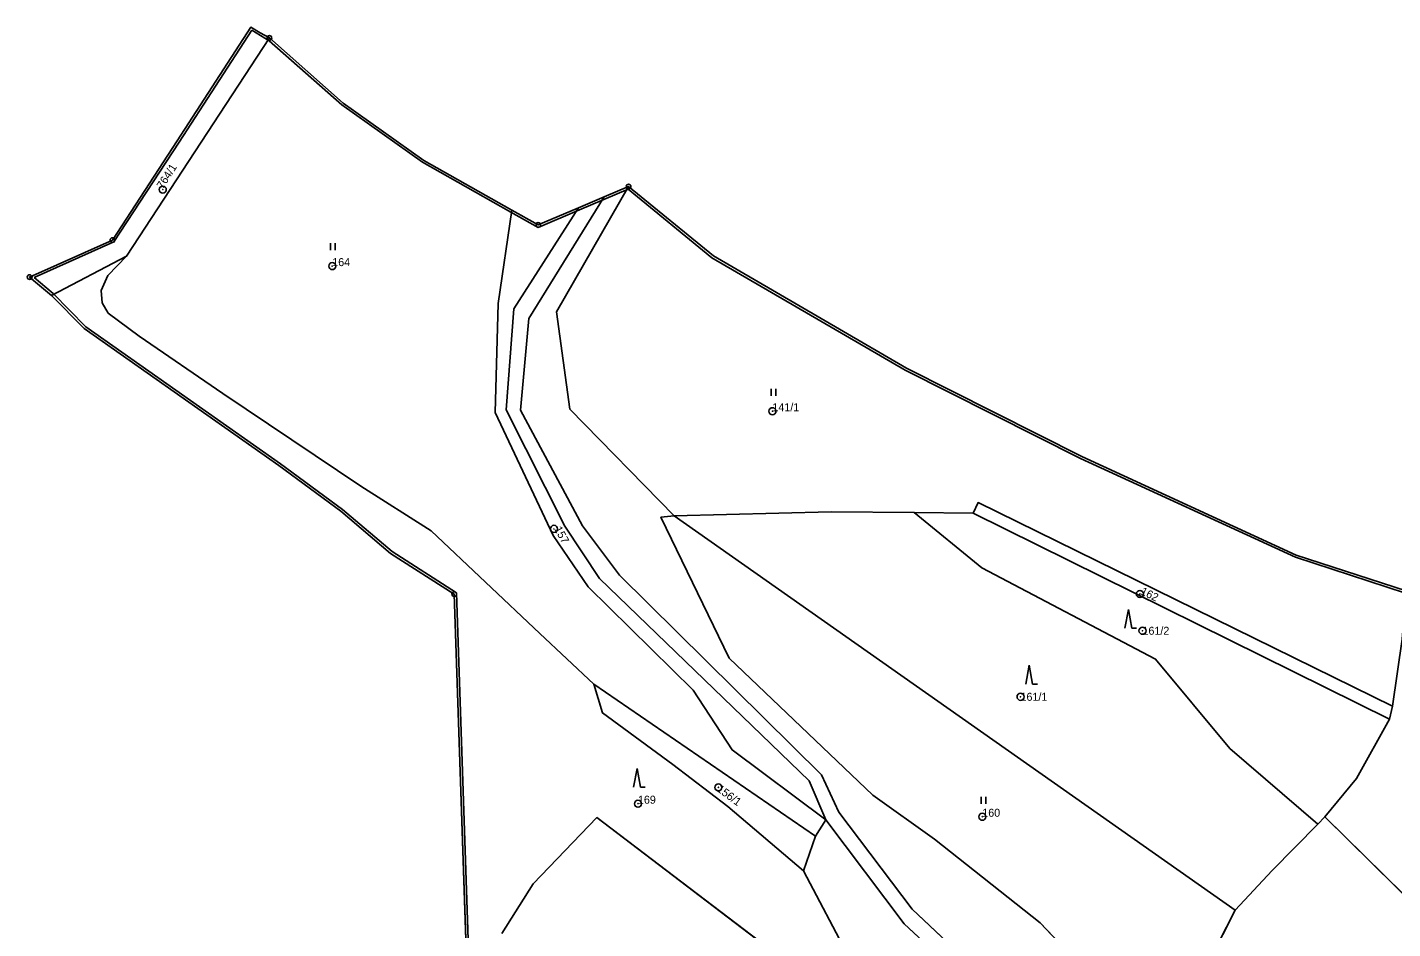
# Model space of a CAD drawing. Extents: x -652854 to -650068, y -1097661 to -1095417.
# Drawn here: x -651109.6 to -650819.6, y -1095608.5 to -1095417 of the extents above; entities that cross this region are included whole.
import ezdxf

# ---------------------------------------------------------------- set-up
doc = ezdxf.new("R2010")
doc.units = 0
for name, color, linetype in [('Definiční body parcel', 7, 'Continuous'), ('Geodetické body', 7, 'Continuous'), ('Hranice obcí', 7, 'Continuous'), ('Hranice parcel', 7, 'Continuous'), ('Obvody jako plochy', 7, 'Continuous'), ('Ostatní hranice', 7, 'Continuous'), ('Parcelní čísla', 7, 'Continuous'), ('Značky kultur', 7, 'Continuous')]:
    doc.layers.add(name, color=color, linetype=linetype)

msp = doc.modelspace()

# ---------------------------------------------------------------- linework, layer by layer
at = {"layer": 'Definiční body parcel'}
for centre, radius in [((-651080.86, -1095451.52), 0.75), ((-651080.86, -1095451.52), 0.0327), ((-651044.86, -1095467.77), 0.75), ((-651044.86, -1095467.77), 0.0327), ((-650951.35, -1095498.59), 0.75), ((-650951.35, -1095498.59), 0.0327), ((-650997.76, -1095523.58), 0.75), ((-650997.76, -1095523.58), 0.0327), ((-650873.29, -1095537.42), 0.75), ((-650873.29, -1095537.42), 0.0327), ((-650872.74, -1095545.23), 0.75), ((-650872.74, -1095545.23), 0.0327), ((-650898.65, -1095559.26), 0.75), ((-650898.65, -1095559.26), 0.0327), ((-650962.83, -1095578.5), 0.75), ((-650962.83, -1095578.5), 0.0327), ((-650979.92, -1095581.97), 0.75), ((-650979.92, -1095581.97), 0.0327), ((-650906.77, -1095584.74), 0.75), ((-650906.77, -1095584.74), 0.0327)]:
    msp.add_circle(centre, radius, dxfattribs=at)
at = {"layer": 'Geodetické body'}
for centre, radius in [((-651058.22, -1095419.3), 0.5), ((-651058.22, -1095419.3), 0.001), ((-650981.9, -1095450.86), 0.5), ((-650981.9, -1095450.86), 0.001), ((-651001.11, -1095459.02), 0.5), ((-651001.11, -1095459.02), 0.001), ((-651091.57, -1095462.24), 0.5), ((-651091.57, -1095462.24), 0.001), ((-651109.14, -1095470.11), 0.5), ((-651109.14, -1095470.11), 0.001), ((-651018.95, -1095537.44), 0.5), ((-651018.95, -1095537.44), 0.001)]:
    msp.add_circle(centre, radius, dxfattribs=at)
at = {"layer": 'Hranice obcí'}
for p, q in [((-651077.8, -1095441.16), (-651062.16, -1095417.04)), ((-651062.16, -1095417.04), (-651060.16, -1095418.18)), ((-651060.16, -1095418.18), (-651058.22, -1095419.3)), ((-651058.22, -1095419.3), (-651042.54, -1095433.15)), ((-651042.54, -1095433.15), (-651025.41, -1095445.31)), ((-651091.57, -1095462.24), (-651077.8, -1095441.16)), ((-651006.69, -1095455.87), (-651025.41, -1095445.31)), ((-650987.13, -1095453.08), (-650981.9, -1095450.86)), ((-650981.9, -1095450.86), (-650963.9, -1095465.61)), ((-650992.58, -1095455.4), (-650987.13, -1095453.08)), ((-651001.11, -1095459.02), (-651006.69, -1095455.87)), ((-651001.11, -1095459.02), (-650992.58, -1095455.4)), ((-651109.14, -1095470.11), (-651091.57, -1095462.24)), ((-650963.9, -1095465.61), (-650922.86, -1095489.44)), ((-651104.47, -1095473.99), (-651109.14, -1095470.11)), ((-651097.54, -1095481.04), (-651104.47, -1095473.99)), ((-651056.2, -1095510.14), (-651097.54, -1095481.04)), ((-650922.86, -1095489.44), (-650885.63, -1095508.23)), ((-651043.02, -1095519.86), (-651056.2, -1095510.14)), ((-650885.63, -1095508.23), (-650840.07, -1095529.15)), ((-651032.46, -1095528.83), (-651043.02, -1095519.86)), ((-651018.95, -1095537.44), (-651032.46, -1095528.83)), ((-650840.07, -1095529.15), (-650816.7, -1095536.76)), ((-651016.16, -1095621.12), (-651018.95, -1095537.44))]:
    msp.add_line(p, q, dxfattribs=at)
at = {"layer": 'Hranice parcel'}
for p, q in [((-651058.22, -1095419.3), (-651088.54, -1095465.64)), ((-650997.25, -1095477.5), (-650981.9, -1095450.86)), ((-651003.09, -1095478.89), (-650987.13, -1095453.08)), ((-651009.63, -1095475.69), (-651006.69, -1095455.87)), ((-651006.31, -1095476.83), (-650992.58, -1095455.4)), ((-651088.54, -1095465.64), (-651104.47, -1095473.99)), ((-651088.54, -1095465.64), (-651092.5, -1095469.77)), ((-651092.5, -1095469.77), (-651093.95, -1095472.98)), ((-651093.95, -1095472.98), (-651093.72, -1095475.56)), ((-651093.72, -1095475.56), (-651092.46, -1095477.73)), ((-651092.46, -1095477.73), (-651085.87, -1095482.66)), ((-651010.22, -1095498.84), (-651009.63, -1095475.69)), ((-651007.89, -1095498.28), (-651006.31, -1095476.83)), ((-650994.36, -1095498.19), (-650997.25, -1095477.5)), ((-651004.85, -1095498.37), (-651003.09, -1095478.89)), ((-651085.87, -1095482.66), (-651068.08, -1095494.82)), ((-651068.08, -1095494.82), (-651038.82, -1095514.5)), ((-650995.44, -1095522.98), (-651007.89, -1095498.28)), ((-650991.71, -1095522.97), (-651004.85, -1095498.37)), ((-650972.25, -1095520.85), (-650994.36, -1095498.19)), ((-650997.94, -1095525.03), (-651010.22, -1095498.84)), ((-651038.82, -1095514.5), (-651023.83, -1095523.99)), ((-650907.68, -1095517.99), (-650908.72, -1095520.28)), ((-650819.64, -1095561.23), (-650907.68, -1095517.99)), ((-650972.25, -1095520.85), (-650975.04, -1095521.11)), ((-650975.04, -1095521.11), (-650960.55, -1095551.05)), ((-650938.89, -1095519.94), (-650972.25, -1095520.85)), ((-650972.25, -1095520.85), (-650853.09, -1095604.56)), ((-650921.24, -1095520.14), (-650938.89, -1095519.94)), ((-650908.72, -1095520.28), (-650921.24, -1095520.14)), ((-650921.24, -1095520.14), (-650906.89, -1095531.86)), ((-650908.72, -1095520.28), (-650820.27, -1095563.98)), ((-651023.83, -1095523.99), (-651000.77, -1095545.83)), ((-650988.07, -1095534.16), (-650995.44, -1095522.98)), ((-650983.87, -1095533.43), (-650991.71, -1095522.97)), ((-650990.49, -1095535.87), (-650997.94, -1095525.03)), ((-650940.93, -1095575.82), (-650983.87, -1095533.43)), ((-650906.89, -1095531.86), (-650869.95, -1095551.23)), ((-650968.22, -1095557.88), (-650990.49, -1095535.87)), ((-650943.56, -1095577.09), (-650988.07, -1095534.16)), ((-651000.77, -1095545.83), (-650989.26, -1095556.57)), ((-650817.61, -1095546.99), (-650819.64, -1095561.23)), ((-650960.55, -1095551.05), (-650930.04, -1095580.18)), ((-650869.95, -1095551.23), (-650854.16, -1095570.25)), ((-650989.26, -1095556.57), (-650942.18, -1095588.83)), ((-650989.26, -1095556.57), (-650987.44, -1095562.7)), ((-650959.88, -1095570.54), (-650968.22, -1095557.88)), ((-650819.64, -1095561.23), (-650820.27, -1095563.98)), ((-650987.44, -1095562.7), (-650972.53, -1095573.62)), ((-650820.27, -1095563.98), (-650827.25, -1095576.64)), ((-650940.04, -1095585.42), (-650959.88, -1095570.54)), ((-650854.16, -1095570.25), (-650835.5, -1095586.31)), ((-650972.53, -1095573.62), (-650960.82, -1095582.56)), ((-650940.04, -1095585.42), (-650943.56, -1095577.09)), ((-650937.27, -1095583.78), (-650940.93, -1095575.82)), ((-650827.25, -1095576.64), (-650833.99, -1095584.78)), ((-650960.82, -1095582.56), (-650944.79, -1095596.25)), ((-650930.04, -1095580.18), (-650916.96, -1095589.5)), ((-651002.18, -1095598.99), (-650988.69, -1095584.93)), ((-650988.69, -1095584.93), (-650941.03, -1095621.17)), ((-650942.18, -1095588.83), (-650940.04, -1095585.42)), ((-650940.04, -1095585.42), (-650923.38, -1095607.47)), ((-650921.67, -1095604.35), (-650937.27, -1095583.78)), ((-650835.5, -1095586.31), (-650833.99, -1095584.78)), ((-650833.99, -1095584.78), (-650793.83, -1095624.33)), ((-650845.17, -1095596.13), (-650835.5, -1095586.31)), ((-650942.18, -1095588.83), (-650944.79, -1095596.25)), ((-650916.96, -1095589.5), (-650894.47, -1095607.28)), ((-650944.79, -1095596.25), (-650935.02, -1095614.61)), ((-650853.09, -1095604.56), (-650845.17, -1095596.13)), ((-651008.83, -1095609.57), (-651002.18, -1095598.99)), ((-650878.83, -1095644.72), (-650921.67, -1095604.35)), ((-650862.18, -1095622.48), (-650853.09, -1095604.56)), ((-650923.38, -1095607.47), (-650881.16, -1095646.75)), ((-650894.47, -1095607.28), (-650870.79, -1095632.18))]:
    msp.add_line(p, q, dxfattribs=at)
at = {"layer": 'Obvody jako plochy'}
for points in [[(-651088.54, -1095465.64), (-651058.22, -1095419.3), (-651060.16, -1095418.18), (-651062.16, -1095417.04), (-651077.8, -1095441.16), (-651091.57, -1095462.24), (-651109.14, -1095470.11), (-651104.47, -1095473.99)], [(-651092.5, -1095469.77), (-651093.95, -1095472.98), (-651093.72, -1095475.56), (-651092.46, -1095477.73), (-651085.87, -1095482.66), (-651068.08, -1095494.82), (-651038.82, -1095514.5), (-651023.83, -1095523.99), (-651000.77, -1095545.83), (-650989.26, -1095556.57), (-650942.18, -1095588.83), (-650940.04, -1095585.42), (-650959.88, -1095570.54), (-650968.22, -1095557.88), (-650990.49, -1095535.87), (-650997.94, -1095525.03), (-651010.22, -1095498.84), (-651009.63, -1095475.69), (-651006.69, -1095455.87), (-651025.41, -1095445.31), (-651042.54, -1095433.15), (-651058.22, -1095419.3), (-651088.54, -1095465.64)], [(-650908.72, -1095520.28), (-650907.68, -1095517.99), (-650819.64, -1095561.23), (-650817.61, -1095546.99), (-650816.7, -1095536.76), (-650840.07, -1095529.15), (-650885.63, -1095508.23), (-650922.86, -1095489.44), (-650963.9, -1095465.61), (-650981.9, -1095450.86), (-650997.25, -1095477.5), (-650994.36, -1095498.19), (-650972.25, -1095520.85), (-650938.89, -1095519.94), (-650921.24, -1095520.14)], [(-650940.04, -1095585.42), (-650943.56, -1095577.09), (-650988.07, -1095534.16), (-650995.44, -1095522.98), (-651007.89, -1095498.28), (-651006.31, -1095476.83), (-650992.58, -1095455.4), (-651001.11, -1095459.02), (-651006.69, -1095455.87), (-651009.63, -1095475.69), (-651010.22, -1095498.84), (-650997.94, -1095525.03), (-650990.49, -1095535.87), (-650968.22, -1095557.88), (-650959.88, -1095570.54)], [(-650907.68, -1095517.99), (-650908.72, -1095520.28), (-650820.27, -1095563.98), (-650819.64, -1095561.23)], [(-650960.55, -1095551.05), (-650930.04, -1095580.18), (-650916.96, -1095589.5), (-650894.47, -1095607.28), (-650870.79, -1095632.18), (-650866.94, -1095628.35), (-650862.18, -1095622.48), (-650853.09, -1095604.56), (-650972.25, -1095520.85), (-650975.04, -1095521.11)], [(-650845.17, -1095596.13), (-650835.5, -1095586.31), (-650854.16, -1095570.25), (-650869.95, -1095551.23), (-650906.89, -1095531.86), (-650921.24, -1095520.14), (-650938.89, -1095519.94), (-650972.25, -1095520.85), (-650853.09, -1095604.56)], [(-650908.72, -1095520.28), (-650921.24, -1095520.14), (-650906.89, -1095531.86), (-650869.95, -1095551.23), (-650854.16, -1095570.25), (-650835.5, -1095586.31), (-650833.99, -1095584.78), (-650827.25, -1095576.64), (-650820.27, -1095563.98)], [(-650817.61, -1095546.99), (-650819.64, -1095561.23), (-650820.27, -1095563.98), (-650827.25, -1095576.64), (-650833.99, -1095584.78), (-650793.83, -1095624.33), (-650752.15, -1095665.53), (-650735.12, -1095645.14), (-650725.42, -1095633.65), (-650748.84, -1095611.39), (-650782.47, -1095579.91)], [(-650972.53, -1095573.62), (-650960.82, -1095582.56), (-650944.79, -1095596.25), (-650942.18, -1095588.83), (-650989.26, -1095556.57), (-650987.44, -1095562.7)], [(-650942.18, -1095588.83), (-650944.79, -1095596.25), (-650935.02, -1095614.61), (-650927.69, -1095619.32), (-650902.01, -1095634.04), (-650885.23, -1095649.63), (-650870.11, -1095665.52), (-650860.26, -1095680.47), (-650851.38, -1095700.16), (-650840.85, -1095724.23), (-650829.85, -1095751.61), (-650828.36, -1095754.97), (-650825.74, -1095811.08), (-650821.45, -1095812.61), (-650825.13, -1095752.26), (-650838.48, -1095716.55), (-650857.72, -1095677.34), (-650881.16, -1095646.75), (-650923.38, -1095607.47), (-650940.04, -1095585.42)], [(-650755.12, -1095669), (-650752.15, -1095665.53), (-650793.83, -1095624.33), (-650833.99, -1095584.78), (-650835.5, -1095586.31), (-650845.17, -1095596.13), (-650853.09, -1095604.56), (-650862.18, -1095622.48), (-650866.94, -1095628.35), (-650824.98, -1095670.21), (-650789.28, -1095705.95), (-650768.91, -1095684.86), (-650761.09, -1095680.61)]]:
    msp.add_lwpolyline(points, close=True, dxfattribs=at)
for points in [[(-650870.79, -1095632.18), (-650894.47, -1095607.28), (-650916.96, -1095589.5), (-650930.04, -1095580.18), (-650960.55, -1095551.05), (-650975.04, -1095521.11), (-650972.25, -1095520.85), (-650994.36, -1095498.19), (-650997.25, -1095477.5), (-650981.9, -1095450.86), (-650987.13, -1095453.08), (-651003.09, -1095478.89), (-651004.85, -1095498.37), (-650991.71, -1095522.97), (-650983.87, -1095533.43), (-650940.93, -1095575.82), (-650937.27, -1095583.78), (-650921.67, -1095604.35), (-650878.83, -1095644.72)], [(-650878.83, -1095644.72), (-650921.67, -1095604.35), (-650937.27, -1095583.78), (-650940.93, -1095575.82), (-650983.87, -1095533.43), (-650991.71, -1095522.97), (-651004.85, -1095498.37), (-651003.09, -1095478.89), (-650987.13, -1095453.08), (-650992.58, -1095455.4), (-651006.31, -1095476.83), (-651007.89, -1095498.28), (-650995.44, -1095522.98), (-650988.07, -1095534.16), (-650943.56, -1095577.09), (-650940.04, -1095585.42), (-650923.38, -1095607.47), (-650881.16, -1095646.75)], [(-650935.02, -1095614.61), (-650944.79, -1095596.25), (-650960.82, -1095582.56), (-650972.53, -1095573.62), (-650987.44, -1095562.7), (-650989.26, -1095556.57), (-651000.77, -1095545.83), (-651023.83, -1095523.99), (-651038.82, -1095514.5), (-651068.08, -1095494.82), (-651085.87, -1095482.66), (-651092.46, -1095477.73), (-651093.72, -1095475.56), (-651093.95, -1095472.98), (-651092.5, -1095469.77), (-651088.54, -1095465.64), (-651104.47, -1095473.99), (-651097.54, -1095481.04), (-651056.2, -1095510.14), (-651043.02, -1095519.86), (-651032.46, -1095528.83), (-651018.95, -1095537.44), (-651016.16, -1095621.12)], [(-651008.83, -1095609.57), (-651002.18, -1095598.99), (-650988.69, -1095584.93), (-650941.03, -1095621.17)], [(-650941.03, -1095621.17), (-650988.69, -1095584.93), (-651002.18, -1095598.99), (-651008.83, -1095609.57)]]:
    msp.add_lwpolyline(points, dxfattribs=at)
at = {"layer": 'Ostatní hranice'}
for p, q in [((-651077.37, -1095441.44), (-651061.93, -1095417.65)), ((-651061.93, -1095417.65), (-651058.26, -1095419.93)), ((-651058.26, -1095419.93), (-651042.86, -1095433.54)), ((-651042.86, -1095433.54), (-651025.71, -1095445.71)), ((-651091.24, -1095462.6), (-651077.37, -1095441.44)), ((-651025.71, -1095445.71), (-651006.91, -1095456.32)), ((-650992.32, -1095455.81), (-650981.98, -1095451.4)), ((-650964.21, -1095466), (-650981.98, -1095451.4)), ((-651006.91, -1095456.32), (-651001.15, -1095459.56)), ((-651001.15, -1095459.56), (-650992.32, -1095455.81)), ((-651108.2, -1095470.22), (-651091.24, -1095462.6)), ((-650964.21, -1095466), (-650923.18, -1095489.89)), ((-651104.12, -1095473.6), (-651108.2, -1095470.22)), ((-651097.2, -1095480.65), (-651104.12, -1095473.6)), ((-651055.87, -1095509.74), (-651097.2, -1095480.65)), ((-650923.18, -1095489.89), (-650885.92, -1095508.63)), ((-651042.68, -1095519.46), (-651055.87, -1095509.74)), ((-650885.92, -1095508.63), (-650840.26, -1095529.6)), ((-651032.14, -1095528.42), (-651042.68, -1095519.46)), ((-651018.47, -1095537.15), (-651032.14, -1095528.42)), ((-650840.26, -1095529.6), (-650816.84, -1095537.23)), ((-651015.67, -1095621.16), (-651018.47, -1095537.15))]:
    msp.add_line(p, q, dxfattribs=at)
at = {"layer": 'Značky kultur'}
for p, q in [((-651045.257, -1095462.915), (-651045.257, -1095464.415)), ((-651044.235, -1095464.415), (-651044.235, -1095462.915)), ((-650951.627, -1095493.815), (-650951.627, -1095495.315)), ((-650950.605, -1095495.315), (-650950.605, -1095493.815)), ((-650875.732, -1095540.689), (-650876.465, -1095544.689)), ((-650875.732, -1095540.689), (-650874.999, -1095544.689)), ((-650874.999, -1095544.689), (-650873.999, -1095544.689)), ((-650896.812, -1095552.549), (-650897.545, -1095556.549)), ((-650896.812, -1095552.549), (-650896.079, -1095556.549)), ((-650896.079, -1095556.549), (-650895.079, -1095556.549)), ((-650980.122, -1095574.479), (-650980.855, -1095578.479)), ((-650980.122, -1095574.479), (-650979.389, -1095578.479)), ((-650979.389, -1095578.479), (-650978.389, -1095578.479)), ((-650907.047, -1095580.505), (-650907.047, -1095582.005)), ((-650906.025, -1095582.005), (-650906.025, -1095580.505))]:
    msp.add_line(p, q, dxfattribs=at)

# ---------------------------------------------------------------- texts
at = {"layer": 'Parcelní čísla'}
for s, rotation, p in [('764/1', 57.339, (-651080.86, -1095451.52)), ('157', 298.737, (-650997.76, -1095523.58)), ('162', 334.359, (-650873.29, -1095537.42)), ('156/1', 323.649, (-650963.334, -1095579.185))]:
    msp.add_text(s, height=1.7, rotation=rotation, dxfattribs=at).set_placement(p)
for s, p in [('164', (-651044.86, -1095467.77)), ('141/1', (-650951.35, -1095498.59)), ('161/2', (-650872.74, -1095546.08)), ('161/1', (-650898.65, -1095560.11)), ('169', (-650979.92, -1095581.97)), ('160', (-650906.77, -1095584.74))]:
    msp.add_text(s, height=1.7, dxfattribs=at).set_placement(p)

doc.saveas('drawing.dxf')
